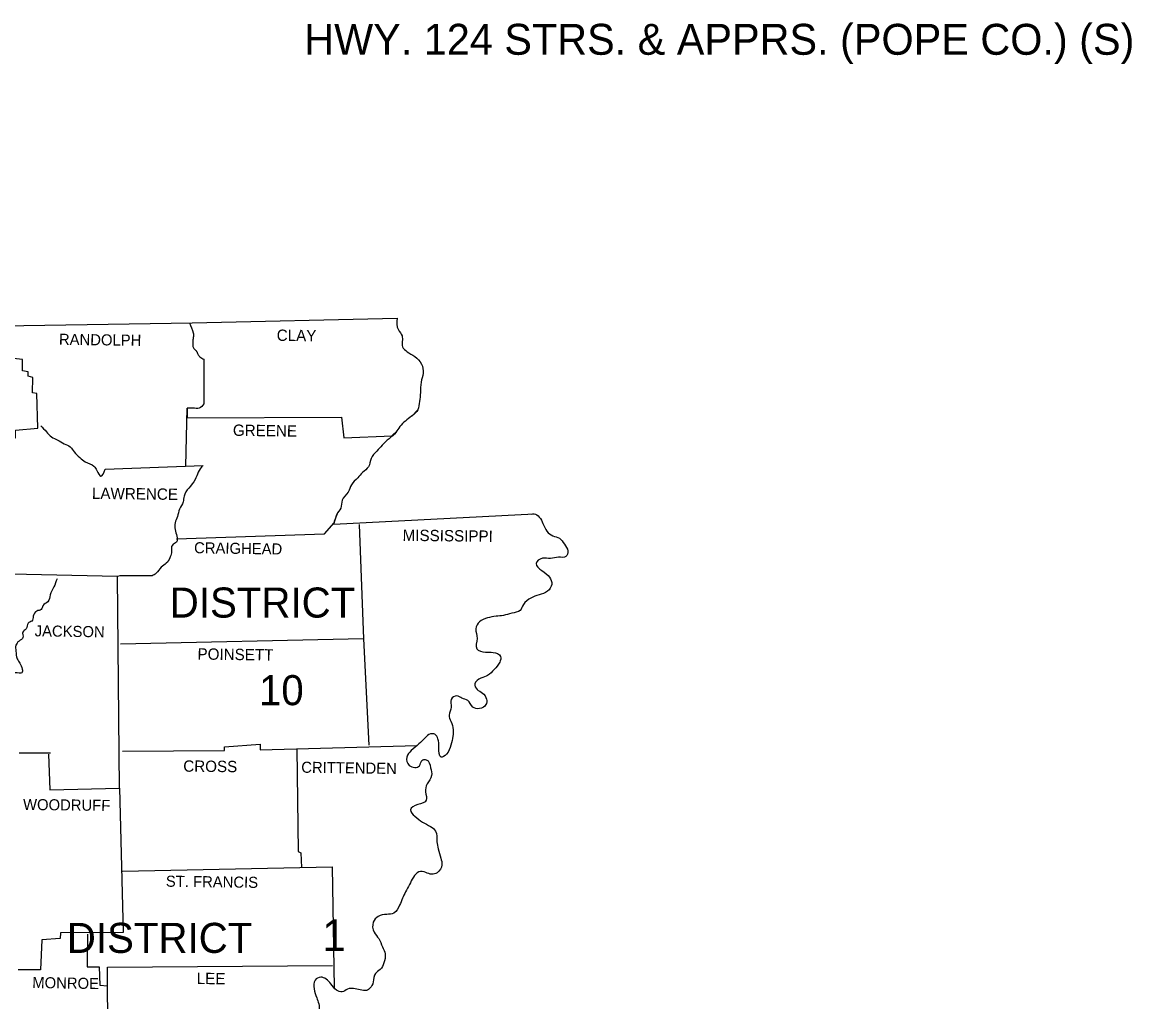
# Model space of a CAD drawing. Extents: x 1373862 to 1376999, y 1168398 to 1170455.
# Drawn here: x 1376569.3 to 1376989.7, y 1170026.9 to 1170398.2 of the extents above; entities that cross this region are included whole.
import ezdxf

# ---------------------------------------------------------------- set-up
doc = ezdxf.new("R2010")
doc.units = 0
doc.layers.add('1', color=7, linetype='Continuous')
doc.layers.add('R_Draft', color=7, linetype='Continuous')

msp = doc.modelspace()

# ---------------------------------------------------------------- linework, layer by layer
at = {"layer": 'R_Draft'}
for p, q in [((1376716.92, 1170248.9), (1376719.09, 1170251.07)), ((1376709.39, 1170241.37), (1376711.48, 1170243.46)), ((1376637.5, 1170230), (1376637.8, 1170230.1)), ((1376687.3, 1170207.9), (1376688.5, 1170211.6)), ((1376687.6, 1170209.1), (1376688.8, 1170212)), ((1376568.1, 1170121.3), (1376580, 1170121.3))]:
    msp.add_line(p, q, dxfattribs=at)
for points in [[(1376162.7, 1170281.4), (1376324.4, 1170281.3), (1376466.3, 1170281.6), (1376633.7, 1170284.2), (1376711.3, 1170286)], [(1376579.3, 1170120.7), (1376579.8, 1170107.2), (1376606.1, 1170107.9), (1376605.4, 1170188.1), (1376565.1, 1170189), (1376564.2, 1170240.6), (1376566.8, 1170240.7), (1376566.7, 1170243.5), (1376575.2, 1170244.3), (1376574.8, 1170257.4), (1376573.2, 1170257.7), (1376573.3, 1170263.5), (1376571.5, 1170264), (1376571.5, 1170265.7), (1376569.4, 1170266), (1376569.4, 1170270.3), (1376563.7, 1170270.9), (1376563.4, 1170275.7), (1376562.3, 1170276.4), (1376562.1, 1170278), (1376559.8, 1170278.5), (1376559.9, 1170279.7), (1376557.9, 1170280), (1376558.2, 1170282.4)], [(1376638.1, 1170270.4), (1376638.1, 1170253.5)], [(1376631.27, 1170229.87), (1376631.8, 1170251.9), (1376631.8, 1170248.2), (1376690.3, 1170248.5), (1376691.1, 1170240.7), (1376709.46, 1170241.37)], [(1376600.7, 1170228.8), (1376637.8, 1170230.1)], [(1376687.3, 1170207.9), (1376763.2, 1170211.8)], [(1376627.8, 1170202.39), (1376683.8, 1170204.2), (1376687.47, 1170208.43)], [(1376696.9, 1170207.8), (1376698.6, 1170164.5), (1376700.6, 1170124.2)], [(1376618.5, 1170188.3), (1376606.3, 1170188.3), (1376605.4, 1170188.1)], [(1376698.6, 1170164.5), (1376606.5, 1170162.4)], [(1376607.3, 1170121.9), (1376645.9, 1170122.1), (1376646, 1170123.5), (1376659.4, 1170124.5), (1376659.4, 1170122.4), (1376718.97, 1170124.04)], [(1376673.4, 1170122.79), (1376673.9, 1170083.9), (1376674.8, 1170083.3), (1376675.12, 1170077.77)], [(1376606.1, 1170107.9), (1376607.6, 1170053.1), (1376583.8, 1170053), (1376583.7, 1170050.8), (1376576.8, 1170050.4), (1376576.2, 1170039), (1376567.8, 1170039)], [(1376607.3, 1170076.4), (1376686.7, 1170078)], [(1376686.7, 1170078), (1376687.54, 1170032.2)], [(1376594, 1170052.5), (1376593.9, 1170040.1), (1376598.5, 1170040.1), (1376598.7, 1170033.2), (1376601.6, 1170032.9)], [(1376607.3, 1169951.4), (1376615.1, 1169951.9), (1376615, 1169972.2), (1376607.7, 1169972.7), (1376608.1, 1170012.4), (1376601.8, 1170013.3), (1376601.6, 1170040), (1376686.9, 1170040.6)]]:
    msp.add_lwpolyline(points, dxfattribs=at)
for points in [[(1376632.74, 1170284.19), (1376634.1, 1170280.4), (1376634.22, 1170279.75), (1376634.17, 1170279.07), (1376634.07, 1170278.39), (1376634.02, 1170278.04), (1376634, 1170277.7), (1376633.99, 1170277.39), (1376633.97, 1170277.08), (1376633.93, 1170276.45), (1376633.93, 1170275.83), (1376633.95, 1170275.51), (1376633.97, 1170275.36), (1376633.99, 1170275.28), (1376634, 1170275.2), (1376634.21, 1170274.72), (1376634.55, 1170274.3), (1376634.95, 1170273.91), (1376635.14, 1170273.71), (1376635.3, 1170273.5), (1376635.46, 1170273.24), (1376635.6, 1170272.96), (1376635.86, 1170272.37), (1376636.17, 1170271.83), (1376636.6, 1170271.4), (1376638.1, 1170270.4)], [(1376711.3, 1170286), (1376711.8, 1170281.6), (1376713.2, 1170279.3), (1376713.4, 1170275.1), (1376715.1, 1170273.3), (1376718, 1170271.5), (1376720.6, 1170268.6), (1376721.2, 1170265.2), (1376720.4, 1170261.7), (1376720.2, 1170257.8), (1376719.8, 1170254.4), (1376719.2, 1170251.3), (1376716.8, 1170248.8), (1376714.5, 1170247), (1376712.4, 1170244.9), (1376710.9, 1170242.7), (1376708.3, 1170240.3), (1376705.7, 1170237.8), (1376703.6, 1170235.6), (1376701.5, 1170232.8), (1376700.5, 1170229.7), (1376698.2, 1170227.5), (1376696.4, 1170225.5), (1376694, 1170222.8), (1376692.8, 1170220.1), (1376690.5, 1170217), (1376690, 1170214), (1376688.5, 1170211.6), (1376688.4, 1170211.2)], [(1376711.3, 1170286), (1376711.8, 1170281.6), (1376713.2, 1170279.3), (1376713.4, 1170275.1), (1376715.1, 1170273.3), (1376718, 1170271.5), (1376720.6, 1170268.6), (1376721.2, 1170265.2), (1376720.4, 1170261.7), (1376720.2, 1170257.8), (1376719.8, 1170254.4), (1376719.2, 1170251.3), (1376716.8, 1170248.8), (1376714.5, 1170247), (1376712.4, 1170244.9), (1376710.9, 1170242.7), (1376708.3, 1170240.3), (1376705.7, 1170237.8), (1376703.6, 1170235.6), (1376701.5, 1170232.8), (1376700.5, 1170229.7), (1376698.2, 1170227.5), (1376696.4, 1170225.5), (1376694, 1170222.8), (1376692.8, 1170220.1), (1376690.5, 1170217), (1376690, 1170214), (1376688.5, 1170211.6), (1376688.4, 1170211.2)], [(1376638.1, 1170253.5), (1376636.4, 1170251.9), (1376633.9, 1170251.9), (1376631.8, 1170251.9)], [(1376576.3, 1170245.2), (1376578.5, 1170242.9), (1376580.4, 1170241), (1376582.6, 1170239.9), (1376585.2, 1170238.4), (1376587.5, 1170237.2), (1376589, 1170235.3), (1376591.1, 1170233.2), (1376593.2, 1170231.5), (1376596.5, 1170229.9), (1376597.6, 1170228.2), (1376599.1, 1170226.1), (1376600.7, 1170228.8)], [(1376637.5, 1170230), (1376636, 1170227.6), (1376634.8, 1170224.8), (1376632.4, 1170221.6), (1376630.6, 1170218.5), (1376630.3, 1170216.4), (1376628.9, 1170213.6), (1376628.1, 1170210.8), (1376627.2, 1170208.4), (1376627.2, 1170205.9), (1376627.9, 1170203.4), (1376627.7, 1170201.1), (1376626.2, 1170200), (1376625.8, 1170197.1), (1376625.2, 1170195.1), (1376623.9, 1170193.1), (1376622, 1170191.6), (1376620, 1170189.3), (1376618.5, 1170188.3)], [(1376762.1, 1170211.7), (1376763.2, 1170211.8), (1376766.6, 1170208.2), (1376768.1, 1170205.2), (1376770.3, 1170203.5), (1376772.8, 1170202.6), (1376774.7, 1170200.3), (1376776, 1170197.8), (1376775.3, 1170195.6), (1376772.5, 1170195.4), (1376769.4, 1170194.9), (1376766.4, 1170195), (1376764, 1170193), (1376766.2, 1170190.3), (1376769.1, 1170187.8), (1376769.9, 1170185.1), (1376768.3, 1170182.5), (1376765.1, 1170181.1), (1376762, 1170179.9), (1376759.2, 1170177.5), (1376757.9, 1170175.2), (1376754.8, 1170174.2), (1376751.6, 1170173.3), (1376748.8, 1170173), (1376745.6, 1170172.4), (1376742.5, 1170170.9), (1376741.2, 1170168.3), (1376741.6, 1170164.6), (1376741.5, 1170160.7), (1376744.8, 1170159.4), (1376747.7, 1170159.3), (1376750.5, 1170157.8), (1376750.2, 1170155.6), (1376748.1, 1170152.8), (1376745.6, 1170150.6), (1376743.1, 1170149.5), (1376740.8, 1170147.4), (1376741.6, 1170145.3), (1376743.7, 1170143.9), (1376745.2, 1170141.6), (1376745, 1170139.5), (1376742.6, 1170138), (1376740, 1170138.6), (1376738.1, 1170141.1), (1376735.9, 1170141.9), (1376734, 1170142.8), (1376731.8, 1170141.5), (1376731.8, 1170138.6), (1376731, 1170135.5), (1376731.7, 1170133.2), (1376732.6, 1170130), (1376732.5, 1170127.6), (1376731.7, 1170124.2), (1376730, 1170120.7), (1376728, 1170119.6), (1376727.2, 1170123.4), (1376726.8, 1170126.5), (1376725.6, 1170128.3), (1376724, 1170128.4), (1376721.9, 1170126.9), (1376719.6, 1170124.6), (1376716.7, 1170122.1), (1376715, 1170119.6), (1376715.9, 1170116.5), (1376718.1, 1170115.7), (1376719.8, 1170116.3), (1376720.7, 1170118.3), (1376722.4, 1170118.6), (1376724, 1170115.5)], [(1376762.1, 1170211.7), (1376763.2, 1170211.8), (1376766.6, 1170208.2), (1376768.1, 1170205.2), (1376770.3, 1170203.5), (1376772.8, 1170202.6), (1376774.7, 1170200.3), (1376776, 1170197.8), (1376775.3, 1170195.6), (1376772.5, 1170195.4), (1376769.4, 1170194.9), (1376766.4, 1170195), (1376764, 1170193), (1376766.2, 1170190.3), (1376769.1, 1170187.8), (1376769.9, 1170185.1), (1376768.3, 1170182.5), (1376765.1, 1170181.1), (1376762, 1170179.9), (1376759.2, 1170177.5), (1376757.9, 1170175.2), (1376754.8, 1170174.2), (1376751.6, 1170173.3), (1376748.8, 1170173), (1376745.6, 1170172.4), (1376742.5, 1170170.9), (1376741.2, 1170168.3), (1376741.6, 1170164.6), (1376741.5, 1170160.7), (1376744.8, 1170159.4), (1376747.7, 1170159.3), (1376750.5, 1170157.8), (1376750.2, 1170155.6), (1376748.1, 1170152.8), (1376745.6, 1170150.6), (1376743.1, 1170149.5), (1376740.8, 1170147.4), (1376741.6, 1170145.3), (1376743.7, 1170143.9), (1376745.2, 1170141.6), (1376745, 1170139.5), (1376742.6, 1170138), (1376740, 1170138.6), (1376738.1, 1170141.1), (1376735.9, 1170141.9), (1376734, 1170142.8), (1376731.8, 1170141.5), (1376731.8, 1170138.6), (1376731, 1170135.5), (1376731.7, 1170133.2), (1376732.6, 1170130), (1376732.5, 1170127.6), (1376731.7, 1170124.2), (1376730, 1170120.7), (1376728, 1170119.6), (1376727.2, 1170123.4), (1376726.8, 1170126.5), (1376725.6, 1170128.3), (1376724, 1170128.4), (1376721.9, 1170126.9), (1376719.6, 1170124.6), (1376716.7, 1170122.1), (1376715, 1170119.6), (1376715.9, 1170116.5), (1376718.1, 1170115.7), (1376719.8, 1170116.3), (1376720.7, 1170118.3), (1376722.4, 1170118.6), (1376724, 1170115.5)], [(1376582.5, 1170187.2), (1376581.3, 1170184.1), (1376579.9, 1170181.1), (1376579, 1170178.5), (1376577.1, 1170177), (1376576.5, 1170175.6), (1376574.8, 1170175), (1376573.5, 1170173), (1376572.9, 1170171.2), (1376571.5, 1170170.4), (1376570.8, 1170168.2), (1376569.5, 1170167), (1376569.6, 1170165), (1376568.1, 1170163.6), (1376566.9, 1170162), (1376566.9, 1170159.8), (1376567.4, 1170156.9), (1376568.4, 1170155.2), (1376569.3, 1170153), (1376569.2, 1170151.6), (1376566.7, 1170151.6), (1376564.6, 1170151.2)], [(1376724, 1170115.5), (1376724.4, 1170112.6), (1376722.7, 1170109.5), (1376722.1, 1170106.4), (1376722.4, 1170103.3), (1376719.2, 1170101.6), (1376716.4, 1170099.6), (1376718, 1170097.2), (1376721, 1170095), (1376724, 1170093.3), (1376725.9, 1170091.6), (1376726.4, 1170087.5), (1376726.9, 1170084.9), (1376727.9, 1170081.3), (1376728.3, 1170078.8), (1376726.5, 1170075.8), (1376724.4, 1170075.2), (1376722.2, 1170075.9), (1376719.6, 1170076.1), (1376717.5, 1170074.1), (1376716, 1170071.3), (1376714.5, 1170068.5), (1376713.4, 1170066.1), (1376712.3, 1170063.5), (1376710.1, 1170060.5), (1376707.4, 1170060), (1376704.2, 1170059.2), (1376702.3, 1170057), (1376702.6, 1170053.3), (1376704.4, 1170050.8), (1376705.8, 1170047.7), (1376706.8, 1170045), (1376706.3, 1170041.6), (1376704.9, 1170039.1), (1376703.1, 1170037.6), (1376702.3, 1170034.4), (1376701, 1170032), (1376699.8, 1170031.2), (1376697.4, 1170031.4), (1376694.8, 1170031.9), (1376692.6, 1170031.7), (1376690.5, 1170030.6), (1376688.4, 1170031.3), (1376686.2, 1170033.7), (1376684.4, 1170035.5), (1376682.4, 1170036.2), (1376680.3, 1170035.1), (1376679.9, 1170031.8), (1376680.9, 1170028.4), (1376681.8, 1170023.8), (1376680.9, 1170021), (1376680.6, 1170016.4)], [(1376724, 1170115.5), (1376724.4, 1170112.6), (1376722.7, 1170109.5), (1376722.1, 1170106.4), (1376722.4, 1170103.3), (1376719.2, 1170101.6), (1376716.4, 1170099.6), (1376718, 1170097.2), (1376721, 1170095), (1376724, 1170093.3), (1376725.9, 1170091.6), (1376726.4, 1170087.5), (1376726.9, 1170084.9), (1376727.9, 1170081.3), (1376728.3, 1170078.8), (1376726.5, 1170075.8), (1376724.4, 1170075.2), (1376722.2, 1170075.9), (1376719.6, 1170076.1), (1376717.5, 1170074.1), (1376716, 1170071.3), (1376714.5, 1170068.5), (1376713.4, 1170066.1), (1376712.3, 1170063.5), (1376710.1, 1170060.5), (1376707.4, 1170060), (1376704.2, 1170059.2), (1376702.3, 1170057), (1376702.6, 1170053.3), (1376704.4, 1170050.8), (1376705.8, 1170047.7), (1376706.8, 1170045), (1376706.3, 1170041.6), (1376704.9, 1170039.1), (1376703.1, 1170037.6), (1376702.3, 1170034.4), (1376701, 1170032), (1376699.8, 1170031.2), (1376697.4, 1170031.4), (1376694.8, 1170031.9), (1376692.6, 1170031.7), (1376690.5, 1170030.6), (1376688.4, 1170031.3), (1376686.2, 1170033.7), (1376684.4, 1170035.5), (1376682.4, 1170036.2), (1376680.3, 1170035.1), (1376679.9, 1170031.8), (1376680.9, 1170028.4), (1376681.8, 1170023.8), (1376680.9, 1170021), (1376680.6, 1170016.4)]]:
    msp.add_spline(points, degree=3, dxfattribs=at)

# ---------------------------------------------------------------- texts
at = {"layer": '1'}
msp.add_text('HWY. 124 STRS. & APPRS. (POPE CO.) (S)', height=11.724, dxfattribs=at).set_placement((1376676.15, 1170385.84))
at = {"layer": 'R_Draft'}
for s, height, rotation, p in [('RANDOLPH', 4.201, 359.2583, (1376583.2, 1170275.9)), ('CLAY', 4.3, 359.2258, (1376665.7, 1170277.4)), ('GREENE', 4.301, 359.2361, (1376649.1, 1170241.4)), ('LAWRENCE', 4.301, 359.2678, (1376595.7, 1170217.5)), ('MISSISSIPPI', 4.2996, 359.3097, (1376713.4, 1170201.6)), ('CRAIGHEAD', 4.201, 359.1159, (1376634.4, 1170196.9)), ('JACKSON', 4.199, 359.1352, (1376574, 1170165.4)), ('POINSETT', 4.3, 359.1987, (1376635.7, 1170156.6)), ('CROSS', 4.3, 359.3839, (1376630.3, 1170114.1)), ('CRITTENDEN', 4.201, 359.213, (1376675, 1170113.7)), ('WOODRUFF', 4.199, 359.2748, (1376569.6, 1170099.6)), ('ST. FRANCIS', 4.1994, 359.2216, (1376623.7, 1170070.5)), ('MONROE', 4.199, 359.0331, (1376573.1, 1170032.1)), ('LEE', 4.301, 359.4327, (1376635.4, 1170033.6))]:
    msp.add_text(s, height=height, rotation=rotation, dxfattribs=at).set_placement(p)
for s, height, p in [('DISTRICT', 11.4, (1376625.2, 1170172.5)), ('10', 11.4, (1376659, 1170139.3)), ('DISTRICT', 11.4, (1376586.2, 1170045.4)), ('1', 12, (1376683, 1170046.1))]:
    msp.add_text(s, height=height, dxfattribs=at).set_placement(p)

doc.saveas('drawing.dxf')
